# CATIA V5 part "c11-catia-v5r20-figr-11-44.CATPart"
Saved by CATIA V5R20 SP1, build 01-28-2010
Part number: Part1
Bounding box of the stored display mesh (mm): x -270.607 to 0, y -223.278 to 0, z -13.562 to 46.691
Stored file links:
  D:\v5_r20\psrt_files_downloaded\c11\c11-catia-v5r20-figr-11-44.CATPart
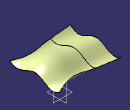
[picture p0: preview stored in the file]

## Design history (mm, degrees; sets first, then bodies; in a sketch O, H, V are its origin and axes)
Set1
  Sweep1: type Unspec, Profile Sketch2, Guide Sketch1
  Extrapol1: ToExtrapol edge of Sweep1, Support Sweep1, Length 100
Body1 (main body)
  Sketch1 on yz-plane, origin (0, 0, 0), H (0, 1, 0), V (0, 0, 1)
    spline S1 through (0, 0) (-40, -10) (-100, 20) (-170, 0) (-220, 10)
    point P1 (0, 0)
    coincidence: P1 O
  Sketch2 on zx-plane, origin (0, 0, 0), H (-1, 0, 0), V (0, 0, 1)
    spline S1 through (0, 0) (60, 30) (121.1814, 19.9844) (171.1814, 9.9844)
    point P1 (0, 0)
    coincidence: P1 O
